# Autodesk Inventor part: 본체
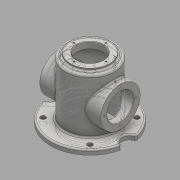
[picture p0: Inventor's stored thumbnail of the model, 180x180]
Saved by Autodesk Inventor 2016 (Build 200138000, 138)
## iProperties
Created: 2018-04
Part Number: 본체
Material: 일반
Document SubType Name: Modeling
Designer: 605-08
Density: 1 g/cm^3
Appearance: 기본값
Author: 605-08
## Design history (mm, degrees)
sketch "스케치1"
  geometry: C1 r 50 at (0, 0); 1 further point
  constraints: 1 centre point, 1 coincident
  dimensions: "d0" = 100 diameter of C1
extrude "돌출1" new body sketch "스케치1" distance "d1" = 8; taper "d2" = 0 deg
sketch "스케치2"
  geometry: A1 r 15 centre (-80, 0) between (-78.594, -14.934) and (-78.594, 14.934); A2 r 15 centre (80, 0) between (78.594, 14.934) and (78.594, -14.934); A3 r 80 centre (0, 0) between (-78.594, -14.934) and (78.594, -14.934); A4 r 80 centre (0, 0) between (78.594, 14.934) and (-78.594, 14.934); 1 further point
  constraints: 8 point on circle, 4 centre point, 1 coincident
  dimensions: "d4" = 30 diameter of A1; "d5" = 30 diameter of A2
extrude "돌출2" join sketch "스케치2" distance "d6" = 10; taper "d7" = 0 deg
sketch "스케치3"
  geometry: C1 r 50 at (0, 0); 1 further point
  constraints: 1 centre point, 1 coincident
  dimensions: "d8" = 100 diameter of C1
extrude "돌출3" join sketch "스케치3" distance "d9" = 110; taper "d10" = 0 deg
sketch "스케치4"
  geometry: C1 r 40 at (0, 0); 1 further point
  constraints: 1 centre point, 1 coincident
  dimensions: "d11" = 80 diameter of C1
extrude "돌출4" join sketch "스케치4" distance "d12" = 5; taper "d13" = 0 deg
sketch "스케치5" dims "d14" = 135
  geometry: L1 (0, 0)-(-80, 0); L2 (0, 0)-(-47.73, 47.73); C1 r 50 at (0, 0) reference; A1 r 15 centre (-80, 0) between (-78.594, -14.934) and (-78.594, 14.934) reference; A2 r 80 centre (0, 0) between (78.594, 14.934) and (-78.594, 14.934) reference; A3 r 15 centre (80, 0) between (78.594, 14.934) and (78.594, -14.934) reference; A4 r 80 centre (0, 0) between (-78.594, -14.934) and (78.594, -14.934) reference; 1 further point
  constraints: 4 end point, 1 coincident, 1 horizontal, 3 other
  dimensions: "d16" = 45 deg angle of L1 L2
hole "구멍1" sketch "스케치5" at (-47.73, 47.73) diameter "d17" = 10; stored, may be unused: countersink angle "d21" = 90 deg, drill point angle "d23" = 118 deg; dims "d18" = 6, "d19" = 4, "d20" = 2, "d22" = 8
sketch "스케치6"
  geometry: L1 (-50, 0)-(50, 0) reference; L2 (0, 0)-(0, 132.481); L3 (80, 8)-(14.934, 8) reference; C1 r 40 at (0, 68); 1 further point
  constraints: 2 end point, 2 vertical alignment, 1 centre point, 1 midpoint, 1 vertical
  dimensions: "d27" = 80 diameter of C1; "d29" = 60 distance from line of C1.centre L3
extrude "돌출5" join sketch "스케치6" stored distance "d30" = 124; taper "d31" = 0 deg
sketch "스케치7"
  geometry: C1 r 45 at (0, 0); 1 further point
  constraints: 1 centre point, 1 coincident
  dimensions: "d32" = 90 diameter of C1
extrude "돌출6" cut sketch "스케치7" distance "d33" = 120; taper "d34" = 0 deg
sketch "스케치8"
  geometry: C1 r 27 at (0, 0); 1 further point
  constraints: 1 centre point, 1 coincident
  dimensions: "d35" = 54 diameter of C1
extrude "돌출7" cut sketch "스케치8" stored distance "d36" = 120; taper "d37" = 0 deg
sketch "스케치9"
  geometry: C1 r 40 at (0, 0) reference; C2 r 27 at (0, 0); 1 further point
  constraints: 1 centre point, 1 coincident
  dimensions: "d38" = 54 diameter of C2
extrude "돌출8" cut sketch "스케치9" stored distance "d39" = 120; taper "d40" = 0 deg
sketch "스케치10"
  geometry: L1 (0, 0)-(-32.5, 0); C1 r 40 at (0, 0) reference; 1 further point
  constraints: 2 end point, 1 horizontal
  dimensions: "d41" = 32.5 distance of L1.start L1.end
hole "구멍2" sketch "스케치10" at (-32.5, 0) diameter "d42" = 3.242; stored, may be unused: countersink angle "d46" = 90 deg, drill point angle "d48" = 118 deg; dims "d43" = 8, "d44" = 4, "d45" = 2, "d47" = 10
sketch "스케치11"
  geometry: L1 (0, 0)-(0, 32.5); C1 r 40 at (0, 0) reference; 1 further point
  constraints: 2 end point, 1 vertical
  dimensions: "d52" = 32.5 distance of L1.start L1.end
hole "구멍3" sketch "스케치11" at (0, 32.5) diameter "d53" = 3.242; stored, may be unused: countersink angle "d57" = 90 deg, drill point angle "d59" = 118 deg; dims "d54" = 8, "d55" = 4, "d56" = 2, "d58" = 10
fillet "모깎기1" dims "d63" = 5
fillet "모깎기2" dims "d64" = 3
chamfer "모따기1" distance "d65" = 1; stored, may be unused: second distance "d66" = 2, angle "d67" = 45 deg
fillet "모깎기3" dims "d68" = 3
node "작업 평면1"
sketch "스케치12"
  geometry: L1 (78.594, 8)-(-78.594, 8) reference; 2 further points
  constraints: 1 vertical alignment, 1 other
  dimensions: "d70" = 70 distance from line of L1 point (0, 78)
feature "엠보싱1" sketch "스케치12" dims "d71" = 0.5, "d72" = 0
node "솔리드1"
pattern_circular "원형 패턴1" dims angle "d25" = 360 deg
pattern_circular "원형 패턴2" dims angle "d50" = 360 deg
mirror "대칭1"
pattern_circular "원형 패턴3" dims angle "d61" = 360 deg
node "투영된 루프1"
node "투영된 루프2"
other parameters: "d69" = 65.25
